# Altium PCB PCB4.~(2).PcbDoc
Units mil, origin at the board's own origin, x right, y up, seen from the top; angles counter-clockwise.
Board outline 5950.03 x 2950.03 mil, 2 copper layers (Top Layer, Bottom Layer); 86 components, 57 nets, 223 pads, 23 vias.
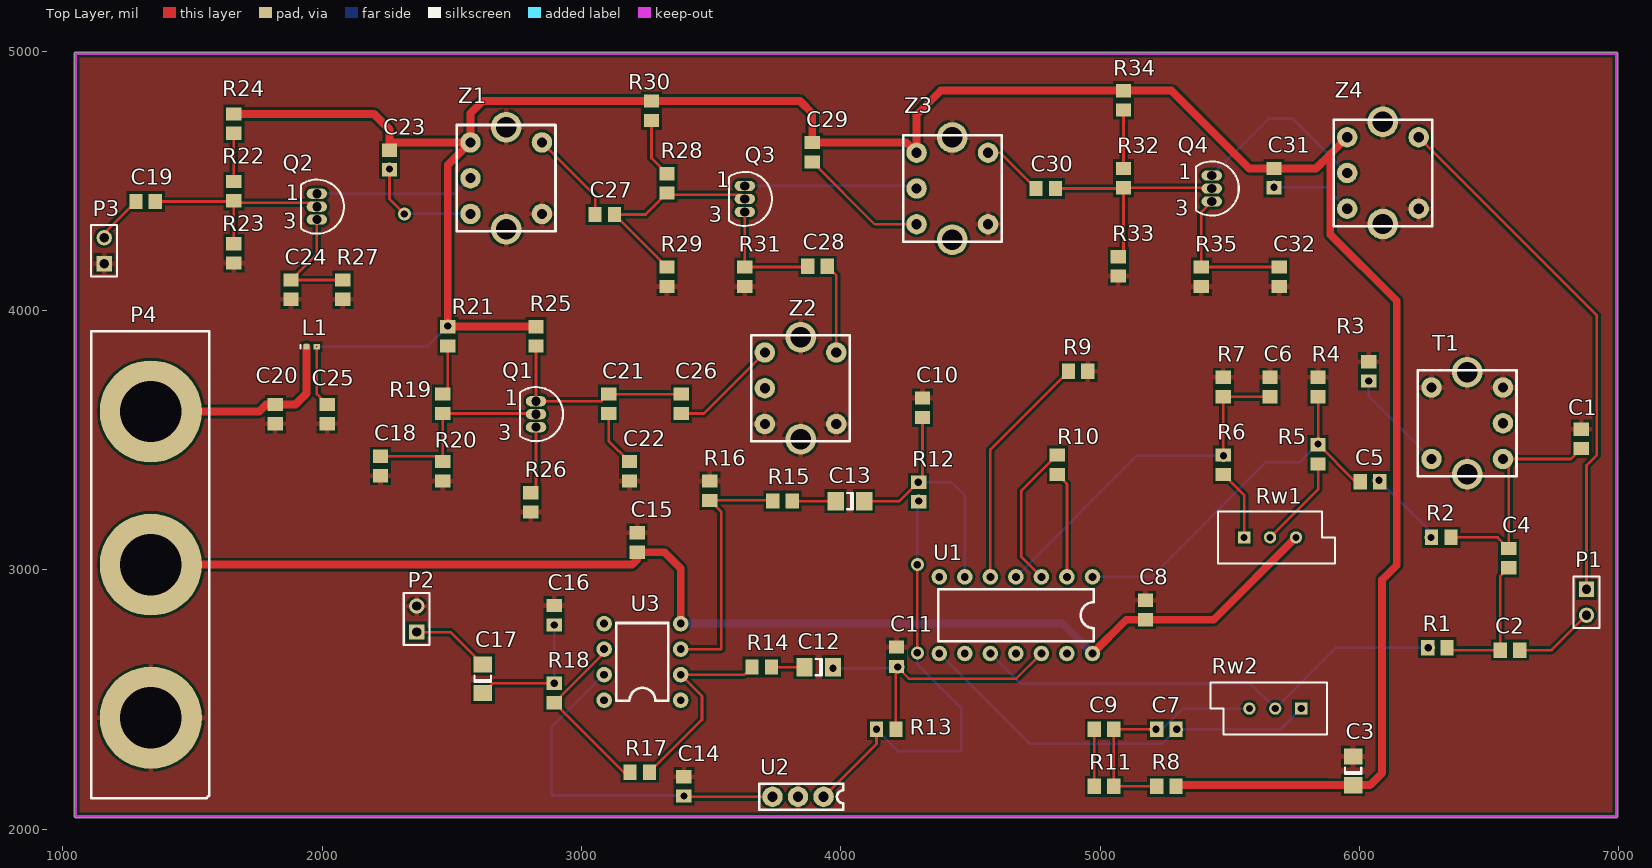
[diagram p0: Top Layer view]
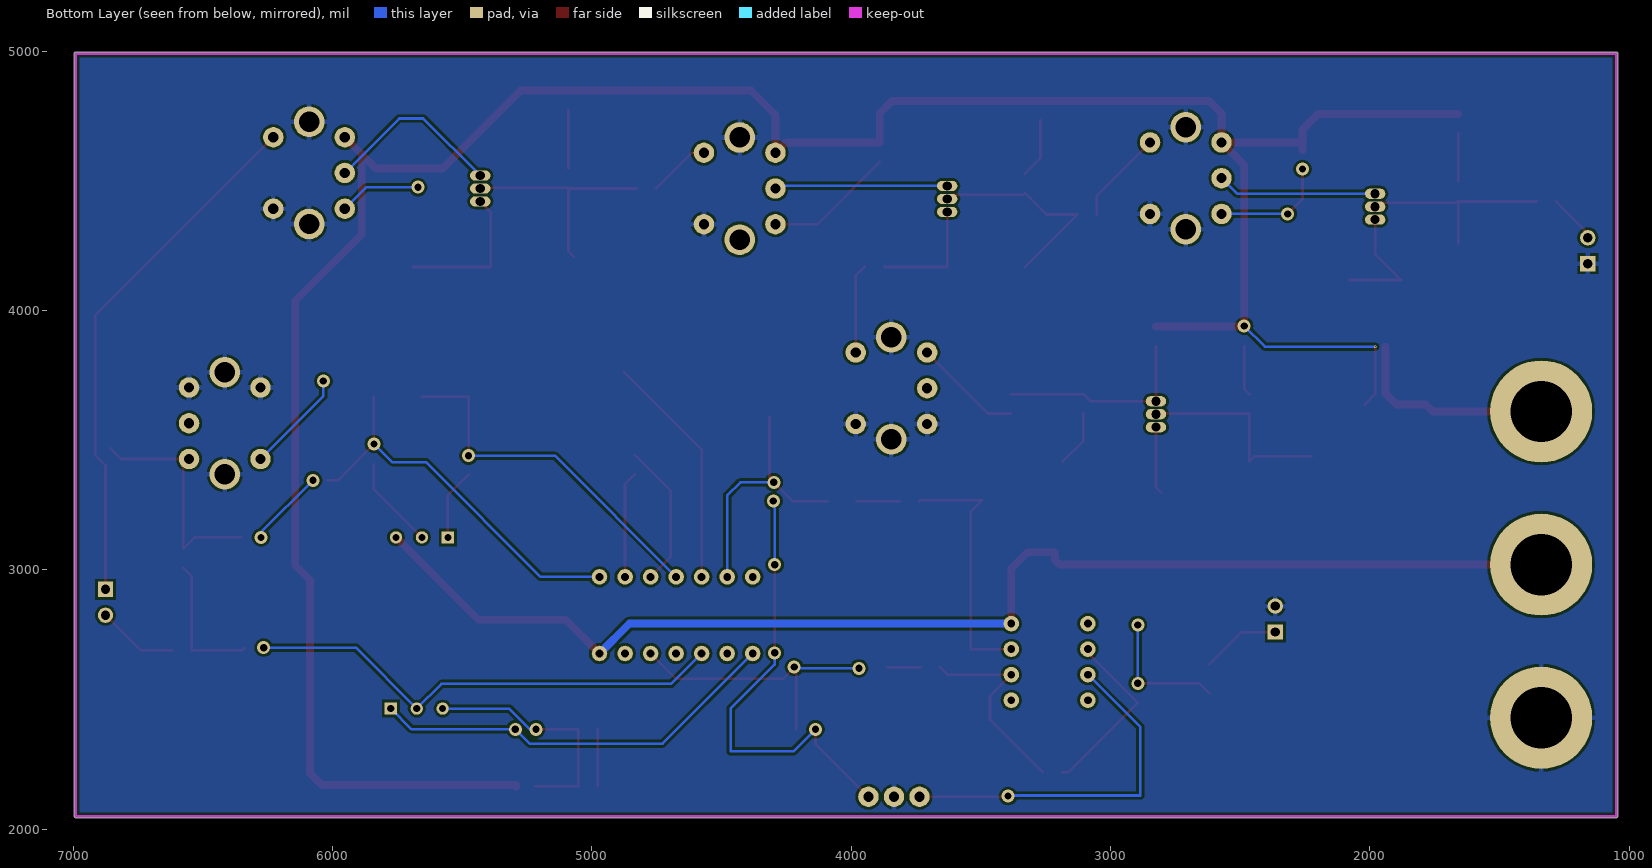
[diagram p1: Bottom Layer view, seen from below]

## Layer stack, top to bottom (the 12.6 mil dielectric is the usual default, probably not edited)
Top Layer: signal copper 1.4
Dielectric: dielectric 12.6, FR-4, Dk 4.8
Bottom Layer: signal copper 1.4

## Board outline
1050,2044.98 cw(c1050,2050) 1044.98,2050 1044.98,4990 cw(c1050,4990) 1050,4995.02 6990,4995.02 cw(c6990,4990) 6995.02,4990 6995.02,2050 cw(c6990,2050) 6990,2044.98

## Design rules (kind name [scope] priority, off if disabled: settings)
Clearance [All] p1: gap=10
HoleSize [All] p1: absolutevalues=TRUE maxlimit=1000 minlimit=1 maxpercent=80.000 minpercent=20.000
HoleToHoleClearance [All] p1: gap=1 allowstackedmicrovias=TRUE
MinimumSolderMaskSliver [All] p1: minsoldermaskwidth=1
PolygonConnect [All] p1: connectstyle=Relief reliefconductorwidth=20 reliefentries=4 polygonreliefangle="90 Angle"
RoomDefinition Sheet2 [InComponentClass('Sheet2')] p1: confinementstyle=ConfineIn formatcopy=TRUE lockcomponents=FALSE outline 0,0 2000,0 2000,1000 0,1000
RoomDefinition Sheet1 [InComponentClass('Sheet1')] p2: confinementstyle=ConfineIn formatcopy=TRUE lockcomponents=FALSE outline 0,0 2000,0 2000,1000 0,1000
RoutingVias [All] p1: holewidth=28 width=50 viastyle="Through Hole" minholewidth=28 minwidth=50 maxholewidth=28 maxwidth=50
SilkscreenOverComponentPads [All] p1: minsilkscreentomaskgap=10
SolderMaskExpansion [All] p1: expansion=4
TestPointUsage [All] p1: valid=0 allowmultiple=FALSE
Testpoint [All] p1: side=15 testpointundercomponent=TRUE minsize=40 maxsize=100 preferedsize=60 minholesize=0 maxholesize=40 preferedholesize=32 testpointgrid=1 style=1023 order=0-112345678
Width [All] p1: maxlimit=100 minlimit=10 preferedwidth=10 toplayer_prefwidth=15 bottomlayer_prefwidth=15 minimp=50.000000 maximp=50.000000 favimp=50.000000
20 further rules are at their usual default settings.

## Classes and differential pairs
component class Sheet1: C1 C2 C3 C4 C5 C6 C7 C8 C9 C10 C11 C12 C13 C14 C15 C16 C17 P1 P2 R1 R2 R3 R4 R5 R6 R7 R8 R9 R10 R11 R12 R13 R14 R15 R16 R17 R18 Rw1 Rw2 T1 U1 U2 U3
component class Sheet2: C18 C19 C20 C21 C22 C23 C24 C25 C26 C27 C28 C29 C30 C31 C32 L1 P3 P4 Q1 Q2 Q3 Q4 R19 R20 R21 R22 R23 R24 R25 R26 R27 R28 R29 R30 R31 R32 R33 R34 R35 Z1 Z2 Z3 Z4

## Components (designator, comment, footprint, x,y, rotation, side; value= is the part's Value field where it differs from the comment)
C1 "Cap" 2012[0805] 6855,3505 r270 top
C2 "Cap" 2012[0805] 6580,2690 r180 top
C3 "Cap Pol1" C1206 5975,2225 r90 top
C4 "Cap" 2012[0805] 6575,3045 r270 top
C5 "Cap" 2012[0805] 6040,3340 r180 top
C6 "Cap" 2012[0805] 5655,3705 r270 top
C7 "Cap" 2012[0805] 5255,2385 r180 top
C8 "Cap" 2012[0805] 5175,2845 r270 top
C9 "Cap" 2012[0805] 5015,2385 r180 top
C10 "Cap" 2012[0805] 4315,3625 r270 top
C11 "Cap" 2012[0805] 4215,2665 r270 top
C12 "Cap Pol1" C1206 3915,2625 r180 top
C13 "Cap Pol1" C1206 4035,3265 r180 top
C14 "Cap" 2012[0805] 3395,2165 r270 top
C15 "Cap" 2012[0805] 3215,3105 r270 top
C16 "Cap" 2012[0805] 2895,2825 r270 top
C17 "Cap Pol1" C1206 2620,2580 r90 top
C18 "Cap" 2012[0805] 2225,3400 r270 top
C19 "Cap" 2012[0805] 1320,4420 r0 top
C20 "Cap" 2012[0805] 1820,3600 r90 top
C21 "Cap" 2012[0805] 3105,3640 r270 top
C22 "Cap" 2012[0805] 3185,3380 r270 top
C23 "Cap" 2012[0805] 2260,4580 r270 top
C24 "Cap" 2012[0805] 1880,4080 r90 top
C25 "Cap" 2012[0805] 2020,3600 r90 top
C26 "Cap" 2012[0805] 3385,3640 r90 top
C27 "Cap" 2012[0805] 3090,4370 r0 top
C28 "Cap" 2012[0805] 3910,4170 r0 top
C29 "Cap" 2012[0805] 3890,4610 r270 top
C30 "Cap" 2012[0805] 4790,4470 r0 top
C31 "Cap" 2012[0805] 5670,4510 r270 top
C32 "Cap" 2012[0805] 5690,4130 r90 top
L1 "Inductor" 0402-A 1960,3860 r0 top
P1 "Header 2" HDR1X2 6875,2925 r270 top
P2 "Header 2" HDR1X2 2365,2760 r90 top
P3 "Header 2" HDR1X2 1160,4180 r90 top
P4 "Header 3" shuru 1340,3020 r90 top
Q1 "NPN" TO-226 2825,3600 r180 top
Q2 "NPN" TO-226 1980,4400 r180 top
Q3 "NPN" TO-226 3630,4430 r180 top
Q4 "NPN" TO-226 5430,4470 r180 top
R1 "Res1" 2012[0805] 6300,2700 r180 top
R2 "Res1" 2012[0805] 6315,3125 r180 top
R3 "Res1" 2012[0805] 6035,3765 r270 top
R4 "Res1" 2012[0805] 5840,3705 r270 top
R5 "Res1" 2012[0805] 5840,3445 r270 top
R6 "Res1" 2012[0805] 5475,3405 r270 top
R7 "Res1" 2012[0805] 5475,3705 r270 top
R8 "Res1" 2012[0805] 5255,2165 r180 top
R9 "Res1" 2012[0805] 4915,3765 r180 top
R10 "Res1" 2012[0805] 4835,3405 r270 top
R11 "Res1" 2012[0805] 5015,2165 r180 top
R12 "Res1" 2012[0805] 4300,3300 r270 top
R13 "Res1" 2012[0805] 4175,2385 r180 top
R14 "Res1" 2012[0805] 3695,2625 r180 top
R15 "Res1" 2012[0805] 3775,3265 r180 top
R16 "Res1" 2012[0805] 3495,3305 r270 top
R17 "Res1" 2012[0805] 3225,2220 r180 top
R18 "Res1" 2012[0805] 2895,2525 r270 top
R19 "Res1" 2012[0805] 2465,3640 r90 top
R20 "Res1" 2012[0805] 2465,3380 r90 top
R21 "Res Adj1" 2012[0805] 2485,3900 r270 top
R22 "Res1" 2012[0805] 1660,4460 r90 top
R23 "Res1" 2012[0805] 1660,4220 r90 top
R24 "Res Adj1" 2012[0805] 1660,4720 r270 top
R25 "Res1" 2012[0805] 2825,3900 r90 top
R26 "Res1" 2012[0805] 2805,3260 r90 top
R27 "Res1" 2012[0805] 2080,4080 r90 top
R28 "Res1" 2012[0805] 3330,4490 r90 top
R29 "Res1" 2012[0805] 3330,4130 r90 top
R30 "Res Adj1" 2012[0805] 3270,4770 r270 top
R31 "Res1" 2012[0805] 3630,4130 r90 top
R32 "Res1" 2012[0805] 5090,4510 r90 top
R33 "Res1" 2012[0805] 5070,4170 r90 top
R34 "Res Adj1" 2012[0805] 5090,4810 r270 top
R35 "Res1" 2012[0805] 5390,4130 r90 top
Rw1 "RPot" VR5 5655,3125 r0 top
Rw2 "RPot" VR5 5675,2465 r180 top
T1 "zhongzhou" zhongzhou 6415,3565 r180 top
U1 "MC1496" MC1496 4675,2825 r180 top
U2 "LM7808" LM7808 3835,2125 r180 top
U3 "LM741" LM741 3235,2645 r180 top
Z1 "zhongzhou1" zhongzhou 2710,4510 r0 top
Z2 "zhongzhou2" zhongzhou 3845,3700 r0 top
Z3 "zhongzhou3" zhongzhou 4430,4470 r0 top
Z4 "zhongzhou4" zhongzhou 6090,4530 r0 top

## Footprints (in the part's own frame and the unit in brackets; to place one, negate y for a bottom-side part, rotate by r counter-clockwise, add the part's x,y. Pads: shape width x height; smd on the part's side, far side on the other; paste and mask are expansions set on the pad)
0402-A [mm] "Chip Inductor; Body 1 x 0.5 mm (LxW typ)"
  rect 0.6x0.5 smd: 1(-0.5,0) 2(0.5,0)
  silkscreen extent -1.1,-0.15 -1.1,0.15
2012[0805] [mm] "Chip Resistor; Body 2.0 x 1.3 mm (LxW typ)"
  rect 1.3x1.5 smd: 1(-0.95,0) 2(0.95,0)
C1206 [mm] "Chip Capacitor; Body 3.2 x 1.6 mm (LxW typ)"
  rect 1.6x1.8 smd: 1(-1.4,0) 2(1.4,0)
  silkscreen extent -0.3,-0.8 0.3,0.8
HDR1X2 [mm] "Connector; Header; 2 Position"
  rect 1.5x1.5 hole 0.9: 1(0,0)
  round 1.5 hole 0.9: 2(2.54,0)
  silkscreen extent -1.27,-1.27 3.81,1.27
LM741 [mil]
  round 60 hole 30: 1(-147.64,147.64) 2(-147.64,49.21) 3(-147.64,-49.21) 4(-147.64,-147.64) 5(147.64,-147.64) 6(147.64,-49.21) 7(147.64,49.21) 8(147.64,147.64)
  silkscreen extent -100,-150 100,150
LM7808 [mm]
  round 2 hole 1: 1(-2.5,0) 2(0,0) 3(2.5,0)
  silkscreen extent -4.44,-1.27 3.81,1.27
MC1496 [mil]
  round 60 hole 30: 1(-295.28,-147.64) 2(-196.85,-147.64) 3(-98.43,-147.64) 4(0,-147.64) 5(98.43,-147.64) 6(196.85,-147.64) 7(295.28,-147.64) 8(295.28,147.64) 9(196.85,147.64) 10(98.43,147.64) 11(0,147.64) 12(-98.43,147.64) 13(-196.85,147.64) 14(-295.28,147.64)
  silkscreen extent -300,-100 300,100
shuru [mm]
  round 10 hole 6: 1(-15,0) 2(0,0) 3(15,0)
  silkscreen extent -22.86,-5.72 22.86,5.84
TO-226 [mm] "TO, Flat Index; 3 In-Line, Axial Leads; Body Dia. 4.8mm; Leads 0.55 x 0.51 mm (max)"
  oval 2x1 hole 0.9: 1(0,-1.27) 2(0,0) 3(0,1.27)
  silkscreen extent -2.65,-2.65 1.55,2.65
VR5 [mm] "Potentiometer; 3 Leads"
  rect 1.2x1.2 hole 0.7: 1(-2.54,0)
  round 1.2 hole 0.7: 2(0,0) 3(2.54,0)
  silkscreen extent -5.08,-2.54 6.35,2.54
zhongzhou [mm]
  round 2 hole 1: 1(-3.5,3.5) 2(-3.5,0) 3(-3.5,-3.5) 4(3.5,-3.5) 5(3.5,3.5)
  round 3 hole 2: 6(0,5) 7(0,-5)
  silkscreen extent -4.83,-5.21 4.83,5.21

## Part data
C1 C2 C4 C5 C6 C7 C8 C9 C10 C11 C14 C15 C16 C18 C19 C20 C21 C22 C23 C24 C25 C26 C27 C28 C29 C30 C31 C32: "Capacitor"
C3 C12 C13 C17: "Polarized Capacitor (Radial)"
P1 P2 P3: "Header, 2-Pin"
P4: "Header, 3-Pin"
Q1 Q2 Q3 Q4: "NPN Bipolar Transistor"
R1 R2 R3 R4 R5 R6 R7 R8 R9 R10 R11 R12 R13 R14 R15 R16 R17 R18 R19 R20 R22 R23 R25 R26 R27 R28 R29 R31 R32 R33 R35: "Resistor"
R21 R24 R30 R34: "Variable Resistor"
Rw1 Rw2: "Potentiometer"
Z2: library part zhongzhou4
Z3: library part zhongzhou2
Z4: library part zhongzhou3

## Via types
v1: diameter 50, hole 28, Top Layer to Bottom Layer, 22 vias
v2: diameter 10, hole 5, Top Layer to Bottom Layer, 1 vias

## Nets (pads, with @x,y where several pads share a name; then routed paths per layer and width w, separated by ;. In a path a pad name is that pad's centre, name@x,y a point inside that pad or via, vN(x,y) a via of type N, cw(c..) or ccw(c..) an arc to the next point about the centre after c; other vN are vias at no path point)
+12V: C3.1 C23.1 C25.2 C29.1 C31.1 L1.2 R8.1 R21.1 R24.1 R25.2 R30.1 R34.1 Z1.1 Z3.1 Z4.1 | length 10235.6
  Top Layer w10: v2(1979.69,3860) 1979.69,3677.72 C25.2
  Top Layer w30: R24.1 2200,4757.4 2260,4697.4 2260,4647.8 ; C23.1 2260,4647.8 ; R21.1 R21.1@2485,3938 ; R25.2 2825,3938 R21.1@2485,3938 ; R8.1 5292.4,2170 5879,2170 5879.12,2169.88 C3.1 6040,2169.88 6087,2216.88 6087,2962 6143,3018 6143,4037 5887,4293 5887,4602.59 ; Z4.1 5887,4602.59 ; 2260,4647.8 Z1.1 ; R21.1@2485,3938 2485,4560.59 Z1.1 ; Z1.1 2572.2,4760 2619.61,4807.4 R30.1 3842.6,4807.4 3890,4760 C29.1 4252.6,4647.4 Z3.1 4292.2,4754.2 4385.4,4847.4 R34.1 5275,4847.4 5575,4547.4 C31.1 5831.81,4547.4 5887,4602.59
  Bottom Layer w10: v2(1979.69,3860) 2405,3860 v1(2485,3940)
-8V: C8.2 C15.2 P4.2 Rw1.3 U1.14 U3.4 | length 4922.3
  Top Layer w30: P4.2 3195,3020 3215,3040 C15.2 3320,3067.6 3382.64,3004.96 U3.4 ; U1.14 5100.51,2807.6 C8.2 5437.6,2807.6 Rw1.3
  Bottom Layer w30: U3.4 4855,2792.64 U1.14
GND: C1.1 C3.2 C6.1 C8.1 C10.1 C11.1 C14.1 C15.1 C16.1 C18.2 C20.1 C22.2 C24.1 C25.1 C32.1 P2.2 P3.1 P4.1 R3.1 R4.1 R7.1 R9.1 R16.1 R20.1 R23.1 R26.1 R27.1 R29.1 R31.1 R33.1 R35.1 T1.3 T1.4 T1.6 T1.7 U2.2 Z1.4 Z1.6 Z1.7 Z2.3 Z2.4 Z2.6 Z2.7 Z3.4 Z3.6 Z4.4 Z4.6 Z4.7
NetC1_2: C1.2 C4.1 R2.1 T1.1 | length 913.2
  Top Layer w10: R2.1 6532.4,3125 C4.1 6575,3405 T1.1 6814.61,3427.2 C1.2
NetC2_1: C2.1 P1.2 | length 313.5
  Top Layer w10: C2.1 6740,2690 P1.2
NetC2_2: C2.2 C4.2 R1.1 | length 540.4
  Top Layer w10: R1.1 6347.4,2690 C2.2 6542.6,2975.2 C4.2
NetC5_1: C5.1 R2.2 | length 302.8
  Bottom Layer w10: v1(6075,3345) 6275,3145 v1(6275,3125)
NetC5_2: C5.2 R4.2 R5.1 U1.1 | length 1505.8
  Top Layer w10: R5.1@5830,3492.4 R5.1 5841.53,3482.4 5978.93,3345 C5.2@6017.6,3345 ; R5.1@5840,3492.4 R4.2
  Bottom Layer w10: U1.1 5197.64,2972.64 5640,3415 5770,3415 v1(5840,3485)
NetC6_2: C6.2 R6.1 R7.2 U1.4 | length 1398.8
  Top Layer w10: R6.1 R7.2 C6.2
  Bottom Layer w10: U1.4 5142.36,3440 v1(5475,3440)
NetC7_1: C7.1 Rw2.1 U1.8 | length 1595.1
  Bottom Layer w10: U1.8 4727.09,2330 5240,2330 v1(5295,2385) 5695,2385 Rw2.1
NetC7_2: C7.2 C9.1 R8.2 R11.1 Rw2.3 | length 943.5
  Top Layer w10: R8.2 R11.1 C9.1 C7.2
  Bottom Layer w10: v1(5215,2385) 5238.43,2385 5318.43,2465 Rw2.3
NetC9_2: C9.2 R11.2 | length 220
  Top Layer w10: R11.2 C9.2
NetC10_2: C10.2 C13.1 R12.1 U1.6 | length 993.6
  Top Layer w10: C13.1 4226.07,3265 v1(4298.47,3337.4) R12.1 ; C10.2@4312.4,3585 C10.2 R12.1@4315,3352.4
  Bottom Layer w10: v1(4298.47,3337.4) 4427.6,3337.4 4478.15,3286.85 U1.6
NetC11_2: C11.2 C12.1 R13.1 U1.12 | length 1114.2
  Top Layer w10: R13.1 4212.4,2625 C11.2 4262.6,2580 4676.06,2580 U1.12
  Bottom Layer w10: v1(3970,2620) 4215,2620 v1(4220,2625)
NetC12_2: C12.2 R14.1 | length 127.5
  Top Layer w10: R14.1 C12.2
NetC13_2: C13.2 R15.1 | length 167.5
  Top Layer w10: R15.1 C13.2
NetC14_2: C14.2 U2.3 U3.7 | length 1403.3
  Top Layer w10: v1(3395,2127.6) 3397.6,2125 U2.3
  Bottom Layer w10: U3.7 2885,2393.43 2885,2130 3392.6,2130 v1(3395,2127.6)
NetC16_2: C16.2 C17.1 R18.1 | length 515.7
  Top Layer w10: C17.1 2657.52,2562.4 v1(2895,2562.4)
  Bottom Layer w10: v1(2895,2562.4) v1(2895,2787.6)
NetC17_2: C17.2 P2.1 | length 306.7
  Top Layer w10: P2.1 2495.12,2760 C17.2
NetC18_1: C18.1 Q1.2 R19.1 R20.2 | length 794.6
  Top Layer w10: C18.1 2445,3437.4 R20.2 R19.1 2822.4,3602.6 Q1.2
NetC19_1: C19.1 P3.2 | length 190.8
  Top Layer w10: P3.2 1160,4297.4 C19.1
NetC19_2: C19.2 Q2.2 R22.1 R23.2 | length 798.2
  Top Layer w10: C19.2 1657.4,4420 R22.1 ; R23.2 R22.1 ; Q2.2 1964.69,4415.32 1667.28,4415.32 R22.1
NetC20_2: C20.2 L1.1 P4.3 | length 809.1
  Top Layer w30: P4.3 1757.55,3610.55 1784.4,3637.4 C20.2 1897.72,3637.4 1940.32,3680 L1.1
NetC21_1: C21.1 C26.2 Q1.1 R25.1 | length 783.9
  Top Layer w10: R25.1 Q1.1 3077.6,3650 C21.1 C26.2
NetC21_2: C21.2 C22.1 | length 218.3
  Top Layer w10: C21.2 3105,3497.4 C22.1
NetC23_2: C23.2 Z1.3 | length 449.1
  Top Layer w10: C23.2 2260,4429.41 v1(2317.2,4372.2)
  Bottom Layer w10: v1(2317.2,4372.2) Z1.3
  other v1: 2260,4545
NetC24_2: C24.2 Q2.3 R27.2 | length 474
  Top Layer w10: Q2.3 1980,4217.4 C24.2 R27.2
NetC26_1: C26.1 Z2.1 | length 419.6
  Top Layer w10: C26.1 3472.01,3602.6 Z2.1
NetC27_1: C27.1 Z1.5 | length 362.6
  Top Layer w10: Z1.5 3052.6,4442.99 C27.1
NetC27_2: C27.2 Q3.2 R28.1 R29.2 | length 832.7
  Top Layer w10: R29.2 C27.2 3247.4,4370 R28.1 3337.28,4445.32 3614.69,4445.32 Q3.2
NetC28_1: C28.1 Q3.3 R31.2 | length 456.3
  Top Layer w10: Q3.3 R31.2 3870,4167.4 C28.1
NetC28_2: C28.2 Z2.5 | length 346.9
  Top Layer w10: C28.2 3982.8,4134.61 Z2.5
NetC29_2: C29.2 Z3.3 | length 501.8
  Top Layer w10: C29.2 4130.39,4332.2 Z3.3
NetC30_1: C30.1 Z3.5 | length 241.9
  Top Layer w10: Z3.5 4614.8,4607.8 C30.1
NetC30_2: C30.2 Q4.2 R32.1 R33.2 | length 878.2
  Top Layer w10: C30.2 5087.4,4470 R32.1 ; R33.2 5090,4227.4 R32.1 ; Q4.2 5427.4,4472.6 R32.1
NetC31_2: C31.2 Z4.3 | length 316.5
  Bottom Layer w10: v1(5670,4475) 5869.41,4475 Z4.3
NetC32_2: C32.2 Q4.3 R35.2 | length 569.2
  Top Layer w10: Q4.3 5390,4380 R35.2 C32.2
NetQ1_3: Q1.3 R26.2 | length 260.9
  Top Layer w10: R26.2 2825,3317.4 Q1.3
NetQ2_1: Q2.1 Z1.2 | length 617.1
  Bottom Layer w10: Q2.1 2512.2,4450 Z1.2
NetQ3_1: Q3.1 Z3.2 | length 666.3
  Bottom Layer w10: Q3.1 4282.2,4480 Z3.2
NetQ4_1: Q4.1 Z4.2 | length 700.3
  Bottom Layer w10: Q4.1 5650,4740 5742.2,4740 Z4.2
NetR1_2: R1.2 Rw2.2 U1.10 | length 1873.7
  Bottom Layer w10: U1.10 4693.94,2560 5580,2560 Rw2.2 5910,2700 v1(6265,2700)
NetR3_2: R3.2 T1.5 | length 400.7
  Bottom Layer w10: v1(6035,3727.6) 6035,3669.41 T1.5
NetR5_2: R5.2 Rw1.2 | length 359.2
  Top Layer w10: Rw1.2 5840,3310 R5.2
NetR6_2: R6.2 Rw1.1 | length 275.7
  Top Layer w10: R6.2 5555,3287.6 Rw1.1
NetR9_2: R9.2 U1.5 | length 917.1
  Top Layer w10: U1.5 4576.57,3463.98 R9.2
NetR10_1: R10.1 U1.3 | length 561.1
  Top Layer w10: U1.3 4695,3051.06 4695,3303.93 4833.47,3442.4 R10.1
NetR10_2: R10.2 U1.2 | length 410.2
  Top Layer w10: R10.2 4871.85,3330.75 U1.2
NetR12_2: R12.2 R13.2 U2.1 | length 1744.7
  Top Layer w10: U2.1 4137.6,2329.17 v1(4137.6,2385) ; v1(4295,2680) v1(4295,3020)
  Bottom Layer w10: v1(4137.6,2385) 4222.6,2300 4465,2300 4465,2465 4295,2635 v1(4295,2680) ; v1(4295,3020) 4295,3260 v1(4300,3265)
NetR14_2: R14.2 R17.1 U3.2 | length 780.9
  Top Layer w10: R17.1 3465,2422.6 3465,2513.43 U3.2 3628.39,2595.79 R14.2
NetR15_2: R15.2 R16.2 U3.3 | length 991.9
  Top Layer w10: U3.3 3539.21,2694.21 3539.21,3223.39 R16.2 3735,3267.6 R15.2
NetR17_2: R17.2 R18.2 U3.6 | length 690.6
  Top Layer w10: U3.6 3087.36,2678.43 2896.53,2487.6 R18.2 3162.6,2220 R17.2
NetR19_2: R19.2 R21.2 | length 193.5
  Top Layer w10: R19.2 2485,3697.4 R21.2
NetR22_2: R22.2 R24.2 | length 185.2
  Top Layer w10: R22.2 R24.2
NetR28_2: R28.2 R30.2 | length 230
  Top Layer w10: R30.2 3270,4587.4 R28.2
NetR32_2: R32.2 R34.2 | length 225.2
  Top Layer w10: R32.2 R34.2
ZHONGFANG: P1.1 Z4.5 | length 2044
  Top Layer w10: Z4.5 6915,3980.59 6915,3442.48 6875,3402.48 P1.1
pads on no net: T1.2 U1.7 U1.9 U1.11 U1.13 U3.1 U3.5 U3.8 Z2.2 Z3.7

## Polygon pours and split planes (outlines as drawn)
GND on Top Layer "Top Layer-No Net" (solid): 1055,4990 1055,2055 1050,2050 6990,2050 6990,4990
GND on Bottom Layer "Top Layer-No Net" (solid): 1050,4990 1050,2050 6990,2050 6990,4990

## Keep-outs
Keep-Out Layer:
  lines w10: 1050,2050 1050,4990 6990,4990 6990,2050 1050,2050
